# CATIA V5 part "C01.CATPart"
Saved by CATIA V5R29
Part number: C01
Bounding box of the stored display mesh (mm): x -30 to 30, y -40 to 40, z -30 to 230
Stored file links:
  C:\Users\제5강의실-23\Desktop\C01.CATPart
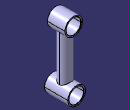
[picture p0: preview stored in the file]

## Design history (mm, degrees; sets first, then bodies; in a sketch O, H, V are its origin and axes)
Body1 (main body)
  Sketch1 on zx-plane, origin (0, 0, 0), H (-1, 0, 0), V (0, 0, 1)
    circle A1 centre (0, 0) radius 30
    radius A1 = 30
  Pad1: profile Sketch1, direction (0, 1, 0), length 40, mirrored extent
  Sketch2 on end face of Pad1, origin (0, 40, 0), H (-1, 0, 0), V (0, 0, 1)
    circle A1 centre (0, 0) radius 25
    radius A1 = 25
  Sketch3 on xy-plane, origin (0, 0, 0), H (1, 0, 0), V (0, 1, 0)
    circle A1 centre (0, 0) radius 20
    radius A1 = 20
  Pad2: profile Sketch3, direction (0, 0, 1), length 200
  Pocket1: profile Sketch2, direction (0, -1, 0), through (limit type 3)
  Sketch4 on zx-plane, origin (0, 0, 0), H (-1, 0, 0), V (0, 0, 1)
    circle A1 centre (0, 200) radius 30
    point P1 (0, 200)
    reference intersected line E1 (-20, 200) -> (20, 200) from end face of Pad2
    radius A1 = 30
    coincidence: P1 V, E1 P1
  Pad3: profile Sketch4, direction (0, 1, 0), length 30, mirrored extent
  Sketch5 on end face of Pad3, origin (0, 30, 0), H (-1, 0, 0), V (0, 0, 1)
    circle A1 centre (0, 200) radius 25
    point P1 (0, 200)
    reference projected circle E1 centre (0, 200) radius 30 from edge [face of Pad3 from Sketch4.A1 | end face of Pad3]
    radius A1 = 25
    coincidence: P1 V
    concentricity: A1 E1
  Pocket2: profile Sketch5, direction (0, -1, 0), through (limit type 3)
  Chamfer1: length 1, angle 45, on edge [end face of Pad1 | face of Pocket1 from Sketch2.A1]; edge [face of Pocket1 from Sketch2.A1 | start face of Pad1]
  Chamfer2: length 1, angle 45, on edge [face of Pocket2 from Sketch5.A1 | start face of Pad3]; edge [end face of Pad3 | face of Pocket2 from Sketch5.A1]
